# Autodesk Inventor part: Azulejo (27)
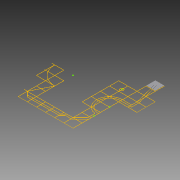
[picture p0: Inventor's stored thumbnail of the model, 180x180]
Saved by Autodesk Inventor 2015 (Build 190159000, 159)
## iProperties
Created: 2015-04
Part Number: Azulejo (27)
Material: Genérico
Document SubType Name: Modeling
Designer: Felipe
Density: 1 g/cm^3
Appearance: Padrão
Author: Felipe
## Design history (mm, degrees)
sketch "Sketch1"
  geometry: L1 (-1510, -7490)-(-1510, -6010); L2 (-3010, -1490)-(-3010, -10); L3 (-2990, 10)-(-1510, 10); L4 (-1510, -10)-(-2990, -10); L5 (-1510, -1490)-(-1510, -10); L6 (-1490, -10)-(-1490, -1490); L7 (-1490, -1490)-(-10, -1490); L8 (-10, -1510)-(-1490, -1510); L9 (-10, -2990)-(-10, -1510); L10 (-10, -5990)-(-10, -4510); L11 (-1490, -7490)-(-10, -7490); L12 (4490, -6010)-(3010, -6010); L13 (10, -1510)-(10, -2990); L14 (10, -3010)-(10, -4490); L15 (10, -4510)-(10, -5990); L16 (10, -5990)-(1490, -5990); L17 (1490, -6010)-(10, -6010); L18 (10, -7490)-(1490, -7490); L19 (1510, -5990)-(2990, -5990); L20 (2990, -6010)-(1510, -6010); L21 (1510, -7490)-(2990, -7490); L22 (4490, 1510)-(4490, 2990); L23 (4490, 10)-(4490, 1490); L24 (4490, -1490)-(4490, -10); L25 (4490, -2990)-(4490, -1510); L26 (3010, -5990)-(4490, -5990); L27 (3010, -7490)-(4490, -7490); L28 (4510, 3010)-(5990, 3010); L29 (5990, 2990)-(4510, 2990); L30 (4510, 2990)-(4510, 1510); L31 (4510, 1510)-(5990, 1510); L32 (5990, 1510)-(5990, 1740.185); L33 (5990, 1760.2)-(5990, 2259.8); L34 (5990, 2279.815)-(5990, 2990); L35 (5990, 1490)-(4510, 1490); L36 (4510, 1490)-(4510, 10); L37 (4510, 10)-(5990, 10); L38 (5990, 10)-(5990, 1490); L39 (5975.983, -10)-(4510, -10); L40 (4510, -10)-(4510, -1490); L41 (5990, -1510)-(5782.897, -1510); L42 (5782.897, -1510)-(5688.66, -1510); L43 (5668.66, -1510)-(5482.895, -1510); L44 (5482.895, -1510)-(5388.656, -1510); L45 (5368.656, -1510)-(4510, -1510); L46 (4510, -1510)-(4510, -2990); L47 (4510, -2990)-(5975.983, -2990); L48 (5990, -2975.728)-(5990, -2837.377); L49 (5990, -2837.377)-(5990, -2536.247); L50 (5990, -2500.476)-(5990, -2317.632); L51 (5990, -2317.632)-(5990, -1510); L52 (5990, -3010)-(4510, -3010); L53 (5990, -4490)-(5990, -3010); L54 (4510, -5990)-(5990, -5990); L55 (5990, -5990)-(5990, -4510); L56 (4510, -7490)-(5990, -7490); L57 (5990, -7490)-(5990, -6310); L58 (5990, -6290)-(5990, -6010); L59 (7490, 4510)-(7490, 5990); L60 (6010, 3010)-(7490, 3010); L61 (7490, 3010)-(7490, 4490); L62 (7490, 2990)-(6010, 2990); L63 (6010, 2990)-(6010, 2279.815); L64 (6010, 2259.8)-(6010, 1760.2)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; A1 r 250 centre (6000, 2010) between (5990, 2259.8) and (5990, 1760.2); A2 r 250 centre (6000, 2010) between (6010, 1760.2) and (6010, 2259.8); A3 r 270 centre (6000, 2010) between (5990, 2279.815) and (5990, 1740.185); A4 r 270 centre (6000, 2010) between (6010, 1740.185) and (6010, 2279.815); A5 r 3010.017 centre (0, 0) between (-1490, -2615.358) and (-346.554, -2990); A6 r 2990.017 centre (0, 0) between (-1490, -2592.316) and (-10, -2990); A7 r 3010.017 centre (0, 0) between (-2603.863, -1510) and (-1510, -2603.863); A8 r 2990.017 centre (0, 0) between (-2580.717, -1510) and (-1510, -2580.717); A9 r 3010.017 centre (0, 0) between (-2990, -346.554) and (-2615.358, -1490); A10 r 2990.017 centre (0, 0) between (-2990, -10) and (-2592.316, -1490); A11 r 2131.367 centre (7500, -1500) between (7490, 631.344) and (6010, 24.017); A12 r 2131.367 centre (7500, -1500) between (5975.983, -10) and (5368.656, -1490); A13 r 2131.367 centre (7500, -1500) between (5368.656, -1510) and (5975.983, -2990); A14 r 2131.367 centre (7500, -1500) between (6010, -3024.017) and (7190, -3608.703); A15 r 1831.367 centre (7500, -1500) between (7490.321, 331.342) and (6463.753, 10); A16 r 1831.367 centre (7500, -1500) between (6435.196, -10) and (6010, -435.196); A17 r 1831.367 centre (7500, -1500) between (5990, -463.753) and (5668.66, -1490); A18 r 1831.367 centre (7500, -1500) between (5668.66, -1510) and (5990, -2536.247); A19 r 1831.367 centre (7500, -1500) between (6010, -2564.804) and (6435.196, -2990); A20 r 1831.367 centre (7500, -1500) between (6463.753, -3010) and (7490, -3331.34); A21 r 2111.367 centre (7500, -1500) between (7490.047, 611.344) and (6024.272, 10); A22 r 2111.367 centre (7500, -1500) between (5990, -24.272) and (5388.656, -1490); A23 r 2111.367 centre (7500, -1500) between (5388.656, -1510) and (5990, -2975.728); A24 r 2111.367 centre (7500, -1500) between (6024.272, -3010) and (7210, -3591.357); A25 r 1811.367 centre (7500, -1500) between (7490.374, 311.342) and (6499.524, 10); A26 r 1811.367 centre (7500, -1500) between (6469.975, -10) and (6010, -469.975); A27 r 1811.367 centre (7500, -1500) between (5990, -499.524) and (5688.66, -1490); A28 r 1811.367 centre (7500, -1500) between (5688.66, -1510) and (5990, -2500.476); A29 r 1811.367 centre (7500, -1500) between (6010, -2530.025) and (6469.975, -2990); A30 r 1811.367 centre (7500, -1500) between (6499.524, -3010) and (7490, -3311.34); A31 r 449.871 centre (7499.449, -4060.672) between (7510, -4510.419) and (7521.546, -4510); 8 further points
  constraints: 698 end point, 64 point on circle, 31 centre point, 11 point on line, 1 other
extrude "Extrusion1" new body sketch "Sketch1" distance "d0" = 60; taper "d1" = 0 deg
extrude "Extrusion2" new body sketch "Sketch1" distance "d2" = 60; taper "d3" = 0 deg
extrude "Extrusion3" new body sketch "Sketch1" distance "d4" = 60; taper "d5" = 0 deg
body "Solid1"
body "Solid2"
body "Solid3"
